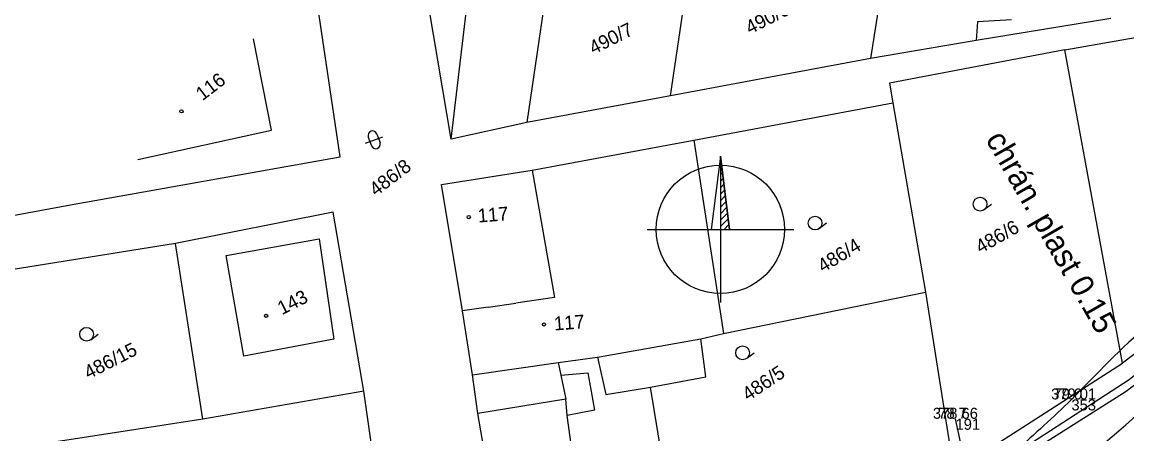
# Model space of a CAD drawing. Extents: x -514509 to -512782, y -1144610 to -1143439.
# Drawn here: x -513652.6 to -513532.1, y -1143721 to -1143676 of the extents above; entities that cross this region are included whole.
import ezdxf

# ---------------------------------------------------------------- set-up
doc = ezdxf.new("R2010")
doc.units = 0
for name, color, linetype in [('Vrstva 10', 7, 'Continuous'), ('Vrstva 12', 7, 'Continuous'), ('Vrstva 13', 7, 'Continuous'), ('Vrstva 46', 7, 'Continuous'), ('Vrstva 57', 7, 'Continuous'), ('Vrstva 58', 7, 'Continuous'), ('Vrstva 59', 7, 'Continuous'), ('Vrstva 60', 7, 'Continuous'), ('Vrstva 62', 7, 'Continuous'), ('Vrstva 8', 7, 'Continuous'), ('Vrstva 9', 7, 'Continuous')]:
    doc.layers.add(name, color=color, linetype=linetype)

msp = doc.modelspace()

# ---------------------------------------------------------------- linework, layer by layer
at = {"layer": 'Vrstva 10'}
for points in [[(-513515.785, -1143698.53), (-513521.525, -1143703.643), (-513529.686, -1143709.146), (-513538.15, -1143717.214), (-513544.213, -1143722.812)], [(-513521.329, -1143748.04), (-513526.723, -1143750.839), (-513529.261, -1143751.622), (-513531.488, -1143751.711), (-513533.089, -1143750.677), (-513534.733, -1143748.79), (-513536.538, -1143745.96), (-513538.306, -1143743.264), (-513540.145, -1143740.206), (-513540.403, -1143737.253), (-513539.926, -1143735.144), (-513539.049, -1143733.832), (-513536.997, -1143731.708), (-513532.775, -1143727.417), (-513522.159, -1143717.523), (-513510.098, -1143705.844)], [(-513557.17, -1143741.564), (-513552.762, -1143736.747), (-513546.656, -1143731.227), (-513536.75, -1143723.745), (-513524.979, -1143713.369)]]:
    msp.add_spline(points, degree=3, dxfattribs=at)
at = {"layer": 'Vrstva 12'}
msp.add_lwpolyline([(-513562.055, -1143736.42), (-513549.28, -1143726.396), (-513550.795, -1143719.319)], dxfattribs=at)
msp.add_lwpolyline([(-513562.055, -1143736.42), (-513549.28, -1143726.396), (-513550.795, -1143719.319)], dxfattribs=at)
at = {"layer": 'Vrstva 13'}
for p, q in [((-513576.441, -1143690.648), (-513576.441, -1143706.648)), ((-513576.441, -1143691.284), (-513576.37, -1143691.213)), ((-513576.441, -1143691.991), (-513576.292, -1143691.842)), ((-513576.441, -1143692.698), (-513576.213, -1143692.47)), ((-513576.441, -1143693.405), (-513576.135, -1143693.099)), ((-513576.441, -1143694.112), (-513576.056, -1143693.728)), ((-513576.441, -1143694.82), (-513575.977, -1143694.356)), ((-513576.441, -1143695.527), (-513575.899, -1143694.985)), ((-513576.441, -1143696.234), (-513575.82, -1143695.613)), ((-513576.441, -1143696.941), (-513575.742, -1143696.242)), ((-513576.441, -1143697.648), (-513575.663, -1143696.87)), ((-513576.441, -1143698.355), (-513575.585, -1143697.499)), ((-513576.027, -1143698.648), (-513575.506, -1143698.127)), ((-513584.441, -1143698.648), (-513568.441, -1143698.648))]:
    msp.add_line(p, q, dxfattribs=at)
for points in [[(-513576.441, -1143690.648), (-513577.441, -1143698.648)], [(-513576.441, -1143690.648), (-513575.441, -1143698.648)], [(-513576.441, -1143690.648), (-513576.441, -1143698.648), (-513575.441, -1143698.648), (-513576.441, -1143690.648)]]:
    msp.add_lwpolyline(points, dxfattribs=at)
msp.add_circle((-513576.441, -1143698.648), 7, dxfattribs=at)
at = {"layer": 'Vrstva 46'}
msp.add_lwpolyline([(-513562.055, -1143736.42), (-513549.28, -1143726.396), (-513550.795, -1143719.319)], dxfattribs=at)
at = {"layer": 'Vrstva 60'}
for p, q in [((-513538.15, -1143717.21), (-513538.15, -1143717.21)), ((-513550.79, -1143719.32), (-513550.79, -1143719.32))]:
    msp.add_line(p, q, dxfattribs=at)
at = {"layer": 'Vrstva 8'}
for p, q in [((-513596.95, -1143692.197), (-513594.529, -1143706.078)), ((-513632.874, -1143719.379), (-513635.868, -1143700.21)), ((-513628.416, -1143712.488), (-513630.356, -1143701.504)), ((-513594.529, -1143706.078), (-513598.767, -1143706.702)), ((-513601.776, -1143707.145), (-513604.558, -1143707.555)), ((-513589.859, -1143712.591), (-513588.945, -1143716.672)), ((-513593.852, -1143714.574), (-513593.287, -1143717.177)), ((-513588.945, -1143716.672), (-513584.055, -1143715.87)), ((-513591.252, -1143732.781), (-513593.146, -1143718.979))]:
    msp.add_line(p, q, dxfattribs=at)
for points in [[(-513605.792, -1143688.805), (-513602.071, -1143657.127), (-513593.426, -1143657.99), (-513594.93, -1143669.125), (-513597.533, -1143686.993)], [(-513533.864, -1143675.635), (-513548.533, -1143678.042), (-513560.068, -1143680.017), (-513581.863, -1143684.07), (-513597.533, -1143686.993), (-513605.792, -1143688.805), (-513610.633, -1143660.108)], [(-513581.863, -1143684.07), (-513578.968, -1143664.349), (-513557.986, -1143666.797), (-513560.068, -1143680.017)], [(-513538.877, -1143679.071), (-513483.704, -1143669.334), (-513513.863, -1143699.065), (-513532.594, -1143713.255)], [(-513661.135, -1143698.528), (-513647.306, -1143695.968), (-513617.922, -1143690.733), (-513620.897, -1143670.627)], [(-513543.007, -1143722.265), (-513531.849, -1143715.02), (-513522.804, -1143707.729), (-513514.307, -1143701.502), (-513507.877, -1143696.134), (-513496.887, -1143686.782), (-513492.629, -1143682.433), (-513485.641, -1143675.148)], [(-513544.681, -1143675.792), (-513548.39, -1143676.007), (-513548.533, -1143678.042)], [(-513639.98, -1143691.013), (-513625.396, -1143687.832), (-513627.365, -1143677.868)], [(-513550.971, -1143725.082), (-513532.594, -1143713.255), (-513538.877, -1143679.071), (-513557.982, -1143682.689), (-513557.626, -1143684.86)], [(-513581.966, -1143752.218), (-513587.854, -1143761.395), (-513594.281, -1143762.879), (-513600.161, -1143734.48), (-513602.904, -1143718.733), (-513603.463, -1143714.542), (-513604.558, -1143707.555), (-513606.849, -1143693.745), (-513596.95, -1143692.197), (-513579.326, -1143688.901), (-513557.626, -1143684.86), (-513554.052, -1143705.501), (-513550.971, -1143725.082), (-513550.631, -1143725.96), (-513581.593, -1143730.936), (-513591.252, -1143732.781), (-513600.161, -1143734.48)], [(-513579.326, -1143688.901), (-513576.115, -1143710.025), (-513554.052, -1143705.501)], [(-513604.988, -1143778.853), (-513607.198, -1143768.145), (-513608.979, -1143756.93), (-513611.621, -1143742.327), (-513615.335, -1143716.305), (-513618.68, -1143696.789), (-513635.868, -1143700.21), (-513656.55, -1143703.499), (-513660.281, -1143704.278), (-513667.963, -1143705.413), (-513649.439, -1143814.036)], [(-513508.331, -1143697.888), (-513520.548, -1143707.483), (-513532.171, -1143716.358), (-513542.292, -1143722.743)], [(-513630.356, -1143701.504), (-513620.209, -1143699.673), (-513618.609, -1143710.63), (-513628.416, -1143712.488)], [(-513615.335, -1143716.305), (-513632.874, -1143719.379), (-513653.366, -1143722.513), (-513656.55, -1143703.499)], [(-513601.776, -1143707.145), (-513598.767, -1143706.702)], [(-513603.463, -1143714.542), (-513594.125, -1143713.188), (-513589.859, -1143712.591), (-513578.579, -1143710.595), (-513576.115, -1143710.025)], [(-513581.593, -1143730.936), (-513584.055, -1143715.87), (-513578.014, -1143714.734), (-513578.579, -1143710.595)], [(-513594.125, -1143713.188), (-513593.852, -1143714.574), (-513590.907, -1143714.298), (-513590.163, -1143718.365), (-513593.146, -1143718.979)], [(-513593.146, -1143718.979), (-513593.287, -1143717.177), (-513602.904, -1143718.733)]]:
    msp.add_lwpolyline(points, dxfattribs=at)
at = {"layer": 'Vrstva 9'}
for p, q in [((-513615.14, -1143689.23), (-513613.261, -1143688.543)), ((-513614.843, -1143688.587), (-513614.5, -1143689.527)), ((-513613.903, -1143688.245), (-513613.561, -1143689.184)), ((-513547.653, -1143696.495), (-513546.862, -1143695.885)), ((-513565.647, -1143698.564), (-513564.856, -1143697.954)), ((-513645.114, -1143710.697), (-513644.323, -1143710.087)), ((-513573.562, -1143712.717), (-513572.771, -1143712.107))]:
    msp.add_line(p, q, dxfattribs=at)
for centre, radius in [((-513635.225, -1143685.775), 0.175), ((-513548.112, -1143695.901), 0.75), ((-513603.882, -1143697.309), 0.175), ((-513566.106, -1143697.97), 0.75), ((-513625.985, -1143708.09), 0.175), ((-513595.677, -1143709.033), 0.175), ((-513645.573, -1143710.103), 0.75), ((-513574.021, -1143712.123), 0.75)]:
    msp.add_circle(centre, radius, dxfattribs=at)
for centre, start, end in [((-513614.373, -1143688.416), 20.00331, 200.00331), ((-513614.031, -1143689.355), 200.00331, 20.00331)]:
    msp.add_arc(centre, 0.5, start, end, dxfattribs=at)

# ---------------------------------------------------------------- texts
at = {"layer": 'Vrstva 57'}
for s, p in [('79 0 ', (-513540.104, -1143717.21)), ('78 7 ', (-513552.673, -1143719.32))]:
    msp.add_text(s, height=1.2, dxfattribs=at).set_placement(p)
at = {"layer": 'Vrstva 58'}
for s, p in [('379 01', (-513540.362, -1143717.21)), ('378 66', (-513553.26, -1143719.32))]:
    msp.add_text(s, height=1.2, dxfattribs=at).set_placement(p)
at = {"layer": 'Vrstva 59'}
for s, p in [('353', (-513538.15, -1143718.41)), ('191', (-513550.79, -1143720.52))]:
    msp.add_text(s, height=1.2, dxfattribs=at).set_placement(p)
at = {"layer": 'Vrstva 62'}
msp.add_text('chrán. plast 0.15', height=2.5, rotation=299.82808, dxfattribs=at).set_placement((-513547.569, -1143688.818))
at = {"layer": 'Vrstva 9'}
for s, rotation, p in [('490/6', 26.99066, (-513573.217, -1143677.403)), ('490/7', 26.59641, (-513590.283, -1143679.602)), ('116', 37.30227, (-513632.932, -1143684.671)), ('486/8', 37.30227, (-513614.01, -1143695.103)), ('117', 4.36014, (-513602.853, -1143697.911)), ('486/6', 29.48307, (-513548.071, -1143701.332)), ('486/4', 31.29155, (-513565.249, -1143703.419)), ('143', 26.99066, (-513624.269, -1143708.032)), ('117', 4.36014, (-513594.535, -1143709.692)), ('486/15', 26.99066, (-513645.367, -1143715.04)), ('486/5', 33.72559, (-513573.417, -1143717.435))]:
    msp.add_text(s, height=1.5, rotation=rotation, dxfattribs=at).set_placement(p)

doc.saveas('drawing.dxf')
